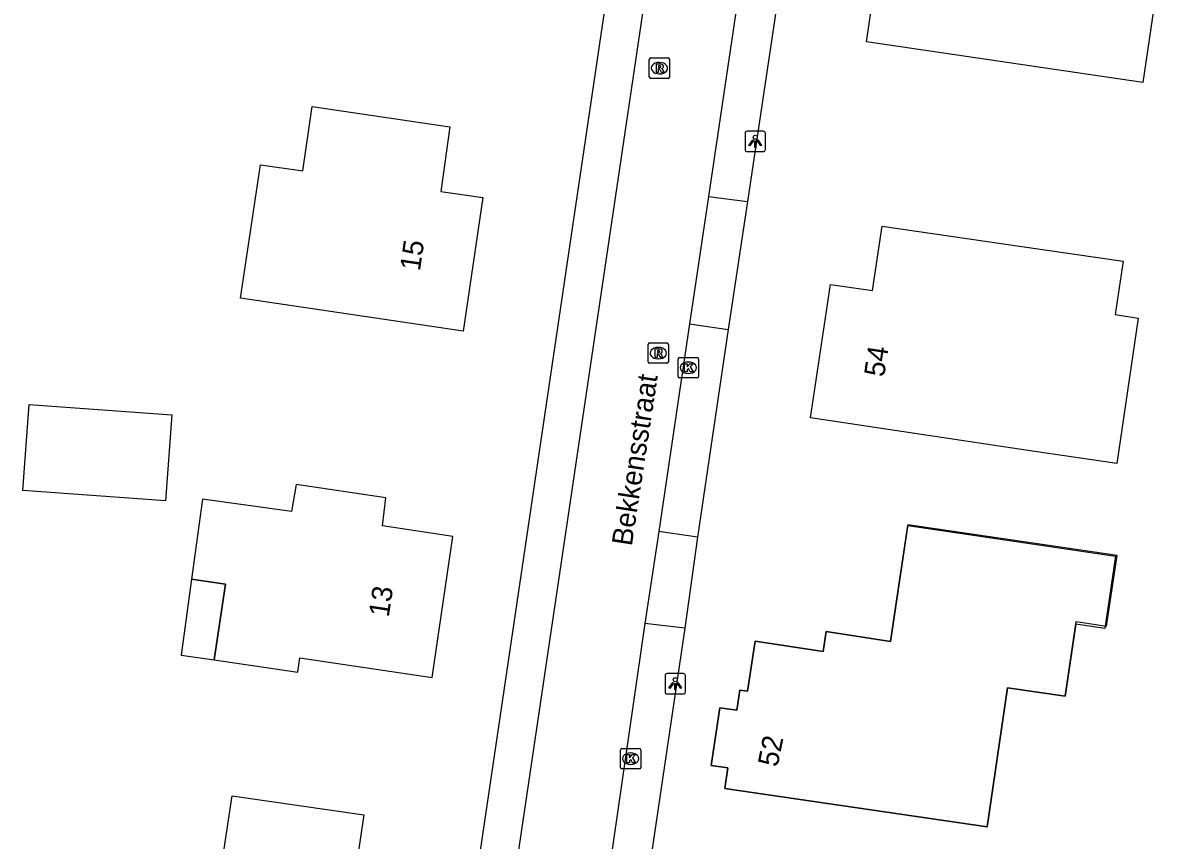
# Model space of a CAD drawing. Extents: x 164150 to 165261, y 382513 to 383432.
# Drawn here: x 164580.3 to 164636.4, y 383078.9 to 383119 of the extents above; entities that cross this region are included whole.
import ezdxf

# ---------------------------------------------------------------- set-up
doc = ezdxf.new("R2010")
doc.units = 0
for name, color, linetype in [('IMGEO_Kolk', 7, 'Continuous'), ('IMGEO_Lichtpunt', 7, 'Continuous'), ('IMGEO_Openbare_ruimte_label', 7, 'Continuous'), ('IMGEO_Pand', 7, 'Continuous'), ('IMGEO_Pand_nummerreeks', 7, 'Continuous'), ('IMGEO_Pand_overbouw', 7, 'Continuous'), ('IMGEO_Pand_vergunning_verleend', 7, 'Continuous'), ('IMGEO_Parkeervlak_open', 7, 'Continuous'), ('IMGEO_Rijbaan_lokaal_open', 7, 'Continuous'), ('IMGEO_Rioolput', 7, 'Continuous'), ('IMGEO_Voetpad_gesloten', 7, 'Continuous'), ('IMGEO_Voetpad_open', 7, 'Continuous')]:
    doc.layers.add(name, color=color, linetype=linetype)

msp = doc.modelspace()

# ---------------------------------------------------------------- linework, layer by layer
at = {"layer": 'IMGEO_Kolk'}
for p, q in [((164612.486, 383101.672), (164612.486, 383102.524)), ((164612.561, 383102.598), (164613.413, 383102.598)), ((164612.974, 383102.378), (164612.999, 383102.378)), ((164613.487, 383102.524), (164613.487, 383101.672)), ((164612.997, 383101.818), (164612.972, 383101.818)), ((164613.413, 383101.598), (164612.561, 383101.598)), ((164609.657, 383082.494), (164609.657, 383083.346)), ((164609.732, 383083.42), (164610.584, 383083.42)), ((164610.658, 383083.346), (164610.658, 383082.494)), ((164610.145, 383083.2), (164610.17, 383083.2)), ((164610.584, 383082.42), (164609.732, 383082.42)), ((164610.168, 383082.64), (164610.143, 383082.64))]:
    msp.add_line(p, q, dxfattribs=at)
for points in [[(164612.486, 383101.672), (164612.486, 383102.524)], [(164612.561, 383102.598), (164613.413, 383102.598)], [(164613.487, 383102.524), (164613.487, 383101.672)], [(164612.807, 383102.298), (164612.93, 383102.298), (164612.93, 383102.147), (164613.06, 383102.298), (164613.224, 383102.298), (164613.078, 383102.147), (164613.231, 383101.898), (164613.079, 383101.898), (164612.994, 383102.062), (164612.93, 383101.995), (164612.93, 383101.898), (164612.807, 383101.898), (164612.807, 383102.298)], [(164613.413, 383101.598), (164612.561, 383101.598)], [(164609.657, 383082.494), (164609.657, 383083.346)], [(164609.732, 383083.42), (164610.584, 383083.42)], [(164610.658, 383083.346), (164610.658, 383082.494)], [(164609.978, 383083.12), (164610.101, 383083.12), (164610.101, 383082.969), (164610.231, 383083.12), (164610.395, 383083.12), (164610.249, 383082.969), (164610.402, 383082.72), (164610.25, 383082.72), (164610.165, 383082.884), (164610.101, 383082.817), (164610.101, 383082.72), (164609.978, 383082.72), (164609.978, 383083.12)], [(164610.584, 383082.42), (164609.732, 383082.42)]]:
    msp.add_lwpolyline(points, dxfattribs=at)
for centre, start, end in [((164612.563, 383102.522), 91.552, 178.448), ((164612.563, 383102.522), 91.552, 178.448), ((164613.411, 383102.522), 1.552, 88.448), ((164613.411, 383102.522), 1.552, 88.448), ((164612.563, 383101.674), 181.552, 268.448), ((164612.563, 383101.674), 181.552, 268.448), ((164613.411, 383101.674), 271.552, 358.448), ((164613.411, 383101.674), 271.552, 358.448), ((164609.734, 383083.344), 91.552, 178.448), ((164609.734, 383083.344), 91.552, 178.448), ((164610.582, 383083.344), 1.552, 88.448), ((164610.582, 383083.344), 1.552, 88.448), ((164609.734, 383082.496), 181.552, 268.448), ((164609.734, 383082.496), 181.552, 268.448), ((164610.582, 383082.496), 271.552, 358.448), ((164610.582, 383082.496), 271.552, 358.448)]:
    msp.add_arc(centre, 0.0765, start, end, dxfattribs=at)
for centre, major_axis, ratio, start_param, end_param in [((164612.973, 383102.098), (-0.387, 0.002), 0.722429, 4.712389, 7.853982), ((164612.998, 383102.098), (-0.39, 0.002), 0.717154, 1.570796, 4.712389), ((164610.144, 383082.92), (-0.387, 0.002), 0.722429, 4.712389, 7.853982), ((164610.169, 383082.92), (-0.39, 0.002), 0.717154, 1.570796, 4.712389)]:
    msp.add_ellipse(centre, major_axis=major_axis, ratio=ratio, start_param=start_param, end_param=end_param, dxfattribs=at)
at = {"layer": 'IMGEO_Lichtpunt'}
for p, q in [((164615.773, 383113.608), (164615.773, 383112.801)), ((164615.773, 383113.608), (164615.773, 383112.801)), ((164616.675, 383113.703), (164615.867, 383113.703)), ((164616.675, 383113.703), (164615.867, 383113.703)), ((164616.769, 383112.801), (164616.769, 383113.608)), ((164616.769, 383112.801), (164616.769, 383113.608)), ((164615.867, 383112.707), (164616.675, 383112.707)), ((164615.867, 383112.707), (164616.675, 383112.707)), ((164611.848, 383086.997), (164611.848, 383086.19)), ((164611.848, 383086.997), (164611.848, 383086.19)), ((164612.75, 383087.092), (164611.942, 383087.092)), ((164612.75, 383087.092), (164611.942, 383087.092)), ((164612.844, 383086.19), (164612.844, 383086.997)), ((164612.844, 383086.19), (164612.844, 383086.997)), ((164611.942, 383086.096), (164612.75, 383086.096)), ((164611.942, 383086.096), (164612.75, 383086.096))]:
    msp.add_line(p, q, dxfattribs=at)
for points in [[(164616.147, 383113.272), (164616.186, 383113.244), (164615.998, 383112.982), (164615.96, 383113.009), (164616.147, 383113.272)], [(164616.249, 383113.224), (164616.296, 383113.224), (164616.296, 383112.902), (164616.249, 383112.902), (164616.249, 383113.224)], [(164616.359, 383113.244), (164616.397, 383113.271), (164616.584, 383113.009), (164616.545, 383112.981), (164616.359, 383113.244)], [(164612.222, 383086.661), (164612.261, 383086.633), (164612.073, 383086.371), (164612.035, 383086.398), (164612.222, 383086.661)], [(164612.324, 383086.613), (164612.371, 383086.613), (164612.371, 383086.291), (164612.324, 383086.291), (164612.324, 383086.613)], [(164612.434, 383086.633), (164612.472, 383086.66), (164612.659, 383086.398), (164612.62, 383086.37), (164612.434, 383086.633)]]:
    msp.add_lwpolyline(points, dxfattribs=at)
for centre in [(164616.272, 383113.406), (164612.347, 383086.795)]:
    msp.add_circle(centre, 0.0994, dxfattribs=at)
for centre, start, end in [((164615.867, 383113.608), 90, 180), ((164615.867, 383113.608), 90, 180), ((164616.675, 383113.608), 0, 90), ((164616.675, 383113.608), 0, 90), ((164615.867, 383112.801), 180, 270), ((164615.867, 383112.801), 180, 270), ((164616.675, 383112.801), 270, 0), ((164616.675, 383112.801), 270, 360), ((164611.942, 383086.997), 90, 180), ((164611.942, 383086.997), 90, 180), ((164612.75, 383086.997), 0, 90), ((164612.75, 383086.997), 0, 90), ((164611.942, 383086.19), 180, 270), ((164611.942, 383086.19), 180, 270), ((164612.75, 383086.19), 270, 0), ((164612.75, 383086.19), 270, 360)]:
    msp.add_arc(centre, 0.0946, start, end, dxfattribs=at)
at = {"layer": 'IMGEO_Pand'}
for points in [[(164621.721, 383118.083), (164622.439, 383122.982), (164625.398, 383122.556), (164625.839, 383125.432), (164636.426, 383123.871), (164635.28, 383116.094), (164621.721, 383118.083)], [(164594.534, 383114.916), (164601.294, 383113.916), (164600.846, 383110.752), (164602.903, 383110.453), (164601.937, 383103.887), (164591.018, 383105.508), (164591.998, 383112.046), (164594.081, 383111.753), (164594.534, 383114.916)], [(164629.877, 383098.009), (164618.979, 383099.634), (164619.956, 383106.19), (164622.016, 383105.891), (164622.499, 383109.048), (164629.23, 383108.066), (164634.311, 383107.325), (164633.921, 383104.705), (164635.062, 383104.535), (164634, 383097.394), (164629.877, 383098.009)], [(164587.652, 383099.786), (164587.342, 383095.568), (164580.344, 383096.082), (164580.654, 383100.3), (164587.652, 383099.786)], [(164588.623, 383091.726), (164590.28, 383091.479), (164589.736, 383087.768), (164593.832, 383087.168), (164593.933, 383087.86), (164600.414, 383086.91), (164601.428, 383093.822), (164597.984, 383094.339), (164598.152, 383095.717), (164593.751, 383096.376), (164593.525, 383095.05), (164589.161, 383095.649), (164588.623, 383091.726)], [(164623.332, 383091.532), (164622.91, 383088.666), (164619.748, 383089.158), (164619.61, 383088.171), (164616.263, 383088.682), (164615.89, 383086.227), (164615.511, 383086.281), (164615.361, 383085.294), (164614.535, 383085.416), (164614.11, 383082.587), (164614.93, 383082.464), (164614.785, 383081.463), (164627.641, 383079.576), (164628.648, 383086.402), (164631.467, 383085.986), (164632.008, 383089.648), (164633.508, 383089.427), (164634.018, 383092.885), (164623.754, 383094.396), (164623.332, 383091.532)], [(164597.068, 383080.159), (164596.621, 383077.189), (164597.958, 383076.991), (164596.394, 383066.366), (164588.593, 383067.513), (164588.857, 383069.348), (164586.505, 383069.731), (164587.274, 383075.049), (164589.65, 383074.705), (164590.61, 383081.103), (164597.068, 383080.159)]]:
    msp.add_lwpolyline(points, dxfattribs=at)
at = {"layer": 'IMGEO_Pand_overbouw'}
msp.add_lwpolyline([(164588.623, 383091.726), (164588.112, 383088.006), (164589.736, 383087.768), (164590.28, 383091.479)], close=True, dxfattribs=at)
at = {"layer": 'IMGEO_Pand_vergunning_verleend'}
msp.add_lwpolyline([(164614.11, 383082.587), (164614.535, 383085.416), (164615.361, 383085.294), (164615.511, 383086.281), (164615.89, 383086.227), (164616.263, 383088.682), (164619.61, 383088.171), (164619.748, 383089.158), (164622.91, 383088.666), (164623.332, 383091.532), (164623.749, 383094.357), (164633.935, 383092.854), (164633.412, 383089.313), (164631.989, 383089.523), (164631.467, 383085.986), (164628.648, 383086.402), (164627.641, 383079.576), (164614.785, 383081.463), (164614.93, 383082.464), (164614.11, 383082.587)], dxfattribs=at)
at = {"layer": 'IMGEO_Parkeervlak_open'}
for points in [[(164614.945, 383103.98), (164613.433, 383093.793)], [(164612.816, 383089.325), (164610.85, 383076.068)]]:
    msp.add_lwpolyline(points, dxfattribs=at)
at = {"layer": 'IMGEO_Rijbaan_lokaal_open'}
for points in [[(164602.804, 383065.865), (164617.29, 383163.645)], [(164616.43, 383127.049), (164613.97, 383110.498)], [(164613.97, 383110.498), (164613.048, 383104.26)], [(164613.048, 383104.26), (164611.544, 383094.072)], [(164611.544, 383094.072), (164610.859, 383089.558)], [(164610.859, 383089.558), (164608.944, 383076.319)]]:
    msp.add_lwpolyline(points, dxfattribs=at)
at = {"layer": 'IMGEO_Rioolput'}
for p, q in [((164611.071, 383116.369), (164611.071, 383117.221)), ((164611.146, 383117.295), (164611.998, 383117.295)), ((164611.559, 383117.075), (164611.584, 383117.075)), ((164612.072, 383117.221), (164612.072, 383116.369)), ((164611.582, 383116.515), (164611.557, 383116.515)), ((164611.998, 383116.295), (164611.146, 383116.295)), ((164611.011, 383102.39), (164611.011, 383103.242)), ((164611.086, 383103.316), (164611.938, 383103.316)), ((164611.499, 383103.096), (164611.524, 383103.096)), ((164612.012, 383103.242), (164612.012, 383102.39)), ((164611.938, 383102.316), (164611.086, 383102.316)), ((164611.522, 383102.536), (164611.497, 383102.536))]:
    msp.add_line(p, q, dxfattribs=at)
for points in [[(164611.071, 383116.369), (164611.071, 383117.221)], [(164611.146, 383117.295), (164611.998, 383117.295)], [(164611.66, 383116.993), (164611.408, 383116.995), (164611.408, 383116.595)], [(164611.586, 383116.914), (164611.532, 383116.914), (164611.532, 383116.833)], [(164612.072, 383117.221), (164612.072, 383116.369)], [(164611.408, 383116.595), (164611.532, 383116.595), (164611.532, 383116.757), (164611.543, 383116.757)], [(164611.532, 383116.833), (164611.584, 383116.833)], [(164611.59, 383116.728), (164611.661, 383116.595), (164611.801, 383116.595), (164611.736, 383116.721)], [(164611.998, 383116.295), (164611.146, 383116.295)], [(164611.011, 383102.39), (164611.011, 383103.242)], [(164611.086, 383103.316), (164611.938, 383103.316)], [(164611.6, 383103.014), (164611.348, 383103.016), (164611.348, 383102.616)], [(164611.526, 383102.935), (164611.472, 383102.935), (164611.472, 383102.854)], [(164612.012, 383103.242), (164612.012, 383102.39)], [(164611.938, 383102.316), (164611.086, 383102.316)], [(164611.348, 383102.616), (164611.472, 383102.616), (164611.472, 383102.778), (164611.483, 383102.778)], [(164611.472, 383102.854), (164611.524, 383102.854)], [(164611.53, 383102.749), (164611.601, 383102.616), (164611.741, 383102.616), (164611.676, 383102.742)]]:
    msp.add_lwpolyline(points, dxfattribs=at)
for centre, radius, start, end in [((164611.148, 383117.219), 0.0765, 91.552, 178.448), ((164611.148, 383117.219), 0.0765, 91.552, 178.448), ((164611.592, 383116.818), 0.0964, 77.0061, 93.1865), ((164611.606, 383116.875), 0.0378, 276.6634, 79.6772), ((164611.659, 383116.883), 0.109, 350.3612, 89.416), ((164611.996, 383117.219), 0.0765, 1.552, 88.448), ((164611.996, 383117.219), 0.0765, 1.552, 88.448), ((164611.148, 383116.371), 0.0765, 181.552, 268.448), ((164611.148, 383116.371), 0.0765, 181.552, 268.448), ((164611.542, 383116.704), 0.0533, 26.0293, 88.6989), ((164611.568, 383117.022), 0.19, 274.7715, 282.9687), ((164611.657, 383116.883), 0.112, 277.5842, 350.9817), ((164611.641, 383116.668), 0.108, 29.5134, 73.7905), ((164611.996, 383116.371), 0.0765, 271.552, 358.448), ((164611.996, 383116.371), 0.0765, 271.552, 358.448), ((164611.088, 383103.24), 0.0765, 91.552, 178.448), ((164611.088, 383103.24), 0.0765, 91.552, 178.448), ((164611.532, 383102.839), 0.0964, 77.0061, 93.1865), ((164611.546, 383102.896), 0.0378, 276.6634, 79.6772), ((164611.599, 383102.904), 0.109, 350.3612, 89.416), ((164611.597, 383102.904), 0.112, 277.5842, 350.9817), ((164611.936, 383103.24), 0.0765, 1.552, 88.448), ((164611.936, 383103.24), 0.0765, 1.552, 88.448), ((164611.088, 383102.392), 0.0765, 181.552, 268.448), ((164611.088, 383102.392), 0.0765, 181.552, 268.448), ((164611.482, 383102.725), 0.0533, 26.0293, 88.6989), ((164611.508, 383103.043), 0.19, 274.7715, 282.9687), ((164611.581, 383102.689), 0.108, 29.5134, 73.7905), ((164611.936, 383102.392), 0.0765, 271.552, 358.448), ((164611.936, 383102.392), 0.0765, 271.552, 358.448)]:
    msp.add_arc(centre, radius, start, end, dxfattribs=at)
for centre, major_axis, ratio, start_param, end_param in [((164611.558, 383116.795), (-0.387, 0.002), 0.722429, 4.712389, 7.853982), ((164611.583, 383116.795), (-0.39, 0.002), 0.717154, 1.570796, 4.712389), ((164611.498, 383102.816), (-0.387, 0.002), 0.722429, 4.712389, 7.853982), ((164611.523, 383102.816), (-0.39, 0.002), 0.717154, 1.570796, 4.712389)]:
    msp.add_ellipse(centre, major_axis=major_axis, ratio=ratio, start_param=start_param, end_param=end_param, dxfattribs=at)
at = {"layer": 'IMGEO_Voetpad_gesloten'}
msp.add_lwpolyline([(164601.081, 383066.812), (164615.508, 383164.456)], dxfattribs=at)
at = {"layer": 'IMGEO_Voetpad_open'}
for points in [[(164618.352, 383126.809), (164615.891, 383110.249)], [(164613.97, 383110.498), (164615.891, 383110.249)], [(164615.891, 383110.249), (164614.945, 383103.98)], [(164613.048, 383104.26), (164614.945, 383103.98)], [(164613.433, 383093.793), (164611.544, 383094.072)], [(164613.433, 383093.793), (164612.816, 383089.325)], [(164612.816, 383089.325), (164610.859, 383089.558)]]:
    msp.add_lwpolyline(points, dxfattribs=at)

# ---------------------------------------------------------------- texts
at = {"layer": 'IMGEO_Openbare_ruimte_label'}
msp.add_text('Bekkensstraat', height=1, rotation=81.3191, dxfattribs=at).set_placement((164610.212, 383093.321))
at = {"layer": 'IMGEO_Pand_nummerreeks'}
for s, rotation, p in [('15', 81.6234, (164599.82, 383106.813)), ('54', 81.5204, (164622.591, 383101.614)), ('13', 81.3379, (164598.289, 383089.834)), ('52', 78.5869, (164617.364, 383082.478))]:
    msp.add_text(s, height=1, rotation=rotation, dxfattribs=at).set_placement(p)

doc.saveas('drawing.dxf')
